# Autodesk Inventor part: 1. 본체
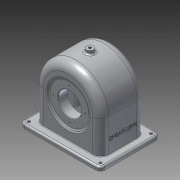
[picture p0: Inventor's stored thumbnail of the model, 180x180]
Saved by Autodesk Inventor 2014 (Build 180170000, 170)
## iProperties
Created: 2016-01
Part Number: 1. 본체
Material: 알루미늄 6061
Document SubType Name: Modeling
Designer: Owner
Density: 2.71 g/cm^3
Appearance: 알루미늄 - 평지
Mass: 809.57 g
Surface Area: 999.65 cm^2
Volume: 298.734 cm^3
Author: Owner
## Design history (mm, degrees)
sketch "스케치1"
  geometry: L1 (-57, 0)-(-57, -64); L2 (-57, -64)-(57, -64); L3 (57, -64)-(57, 0); L4 (51, 0)-(51, -64); L5 (-51, -64)-(-51, 0); A1 r 57 centre (0, 0) between (57, 0) and (-57, 0); A2 r 51 centre (0, 0) between (51, 0) and (-51, 0); 2 further points
  constraints: 10 end point, 4 point on circle, 3 vertical, 2 centre point, 2 perpendicular, 2 point on line, 2 tangent, 1 coincident, 1 midpoint, 1 parallel, 1 vertical alignment
  dimensions: "d1" = 114 diameter of A1; "d2" = 64 distance from line of L2 point (0, 0); "d3" = 6 radial gap between concentric circles of A1 A2; "d4" = 6 distance of L4.end L2.end
extrude "돌출1" new body sketch "스케치1" stored distance "d5" = 77; taper "d6" = 0 deg
extrude "돌출2" cut sketch "스케치1" stored distance "d7" = 67; taper "d8" = 0 deg
sketch "스케치2"
  geometry: L1 (-64, -33.5)-(-64, 33.5) reference; L2 (0, 38.5)-(-64, 38.5) reference; L3 (-64, -38.5)-(0, -38.5) reference; L4 (-4, 38.5)-(-4, -38.5); L5 (57, 38.5)-(0, 38.5) reference; L6 (51, 33.5)-(0, 33.5) reference; L7 (16, 19.5)-(24, 19.5); L8 (24, 19.5)-(35.747, 33.5); L9 (33.416, 38.5)-(30.899, 35.5); L10 (30.899, 35.5)-(16, 35.5); L11 (16, 35.5)-(16, 19.5); L12 (33.416, 38.5)-(35.747, 33.5); L13 (16, 35.5)-(16, 38.5); 1 further point
  constraints: 16 end point, 5 point on line, 3 parallel, 2 perpendicular, 1 collinear
  dimensions: "d9" = 60 distance between parallel lines of L1 L4; "d10" = 50 deg angle of L7 L8; "d12" = 16 distance of L7.start L10.end; "d13" = 5 distance between parallel lines of L9 L8; "d14" = 40 diameter of L11 L4; "d15" = 56 diameter of L7.end L4; "d16" = 3 distance from line of L5 L10.end
revolve "회전1" stored, may be unused: angle "d17" = 90 deg
revolve "회전2" stored, may be unused: angle "d18" = 90 deg
sketch "스케치3"
  geometry: L1 (-57, -64)-(57, -64) reference; C1 r 31 at (0, -4); C2 r 20 at (0, -4); A1 r 57 centre (0, 0) between (57, 0) and (-57, 0) reference
  constraints: 2 centre point, 1 coincident, 1 vertical alignment
  dimensions: "d19" = 62 diameter of C1; "d20" = 60 distance from line of L1 C1.centre; "d21" = 40 diameter of C2
extrude "돌출3" join sketch "스케치3" distance "d22" = 10; taper "d23" = 0 deg
extrude "돌출4" cut sketch "스케치3" stored distance "d24" = 10; taper "d25" = 0 deg
fillet "모깎기1" dims "d26" = 9
fillet "모깎기2" dims "d27" = 14
sketch "스케치4"
  geometry: C1 r 20 at (0, 0) reference; 2 further points
  constraints: 1 vertical alignment
  dimensions: "d28" = 24 distance of C1.centre point (0, 24)
hole "구멍1" sketch "스케치4" at (0, 24) diameter "d29" = 2.459; stored, may be unused: countersink angle "d33" = 90 deg, drill point angle "d35" = 118 deg; dims "d30" = 6, "d31" = 4, "d32" = 2, "d34" = 8
sketch "스케치5"
  geometry: C1 r 34.899 at (0, 0) reference; 2 further points
  constraints: 1 vertical alignment
  dimensions: "d39" = 28 distance of C1.centre point (0, 28)
hole "구멍2" sketch "스케치5" at (0, 28) diameter "d40" = 2.459; stored, may be unused: countersink angle "d44" = 90 deg, drill point angle "d46" = 118 deg; dims "d41" = 7, "d42" = 4, "d43" = 2, "d45" = 9
node "작업 평면1"
sketch "스케치6"
  geometry: L1 (-42, 33.5)-(42, 33.5) reference; L2 (-51, -24.5)-(-51, 24.5) reference; L3 (42, -33.5)-(-42, -33.5) reference; L4 (51, 24.5)-(51, -24.5) reference; L5 (-70, -52)-(70, -52); L6 (70, -52)-(70, 52); L7 (70, 52)-(-70, 52); L8 (-70, 52)-(-70, -52); L9 (-70, -52)-(70, 52); L10 (70, -52)-(-70, 52); A1 r 9 centre (-42, 24.5) between (-42, 33.5) and (-51, 24.5) reference; A2 r 9 centre (-42, -24.5) between (-51, -24.5) and (-42, -33.5) reference; A3 r 9 centre (42, -24.5) between (42, -33.5) and (51, -24.5) reference; A4 r 9 centre (42, 24.5) between (51, 24.5) and (42, 33.5) reference; 1 further point
  constraints: 12 end point, 2 midpoint, 2 parallel, 1 horizontal, 1 perpendicular
  dimensions: "d51" = 140 distance of L7.end L6.end; "d52" = 104 distance of L6.end L5.end
extrude "돌출5" join sketch "스케치6" distance "d53" = 7; taper "d54" = 0 deg
fillet "모깎기3" dims "d55" = 1
sketch "스케치7"
  geometry: L1 (70, 52)-(-70, 52) reference; L2 (-70, 52)-(-70, -52) reference; L3 (-70, -52)-(70, -52) reference; 5 further points
  constraints: 2 horizontal alignment, 2 vertical alignment
  dimensions: "d56" = 8 distance from line of L1 point (-62, 44); "d57" = 8 distance from line of point (-62, 44) L2; "d58" = 124 distance of point (62, 44) point (-62, 44); "d59" = 8 distance from line of L3 point (-62, -44)
hole "구멍3" sketch "스케치7" at (-62, 44), (62, 44), (62, -44), (-62, -44) diameter "d60" = 5; stored, may be unused: countersink angle "d64" = 90 deg, drill point angle "d66" = 118 deg; dims "d61" = 7, "d62" = 4, "d63" = 2, "d65" = 9
fillet "모깎기4" dims "d67" = 8
fillet "모깎기5" dims "d68" = 3
fillet "모깎기6" dims "d69" = 3
node "작업 평면2"
sketch "스케치8"
  geometry: C1 r 6 at (0, 0); 1 further point
  constraints: 1 centre point, 1 coincident
  dimensions: "d71" = 12 diameter of C1
extrude "돌출6" join sketch "스케치8" stored distance "d72" = 7; taper "d73" = 0 deg
hole "구멍4" diameter "d76" = 4.459; stored, may be unused: countersink angle "d80" = 90 deg, drill point angle "d82" = 118 deg; dims "d77" = 7, "d78" = 4, "d79" = 2, "d81" = 9, "d96" = 10, "d97" = 10
fillet "모깎기7" dims "d83" = 3
chamfer "모따기1" distance "d84" = 1; stored, may be unused: second distance "d85" = 2, angle "d86" = 45 deg
chamfer "모따기2" distance "d87" = 1; stored, may be unused: second distance "d88" = 2, angle "d89" = 45 deg
fillet "모깎기8" dims "d90" = 3
fillet "모깎기9" dims "d91" = 3
sketch "스케치9"
  geometry: L1 (-14, 0)-(-14, -56) reference; L2 (68.5, -64)-(-19.5, -64) reference; 2 further points
  constraints: 1 other
  dimensions: "d92" = 38.5 distance from line of L1 point (24.5, -34); "d93" = 30 distance from line of L2 point (24.5, -34)
feature "엠보싱1" sketch "스케치9" dims "d1" = 114, "d2" = 64, "d3" = 6, "d4" = 6, "d94" = 0.5, "d95" = 0
node "솔리드1"
pattern_circular "원형 패턴1" dims angle "d37" = 360 deg
pattern_circular "원형 패턴2" dims angle "d48" = 360 deg
other parameters: "d50" = -64, "d70" = 63
